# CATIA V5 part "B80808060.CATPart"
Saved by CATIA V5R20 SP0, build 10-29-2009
Part number: B80808060
Revision: 2
Definition: design
Nomenclature: B80808060
Source: made
Description: NOT SPECIFIED
Bounding box of the stored display mesh (mm): x -5.85 to 5.85, y -6 to 6, z 0 to 60
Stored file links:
  C:\Users\Raffaele\Desktop\3D X SITO CF\BOLEX\4-PILLAR REF 808\B80808060.CATPart
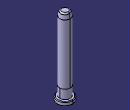
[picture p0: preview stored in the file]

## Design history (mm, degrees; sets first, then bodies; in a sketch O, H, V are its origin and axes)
Body1 "MANIFOLD_SOLID_BREP #450" (main body)
  Solid1: solid without history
